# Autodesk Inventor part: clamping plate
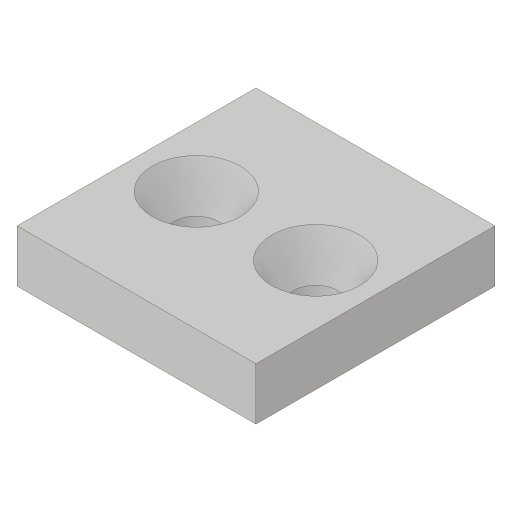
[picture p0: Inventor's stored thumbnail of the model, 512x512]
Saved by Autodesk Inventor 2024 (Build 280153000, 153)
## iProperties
Created: 2016-03
Part Number: clamping plate
Material: Generic
Document SubType Name: Modeling
Designer: Sandeep
Density: 1 g/cm^3
Appearance: Default
Mass: 6.41192 g
Surface Area: 30.6752 cm^2
Volume: 6.41192 cm^3
Author: Sandeep
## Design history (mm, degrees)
sketch "Sketch1"
  geometry: L1 (0, 0)-(32, 0); L2 (32, 0)-(32, 32); L3 (32, 32)-(0, 32); L4 (0, 32)-(0, 0)
  constraints: 8 end point, 2 parallel, 1 horizontal, 1 perpendicular
  dimensions: "d0" = 32 distance between parallel lines of L1 L3; "d1" = 32 distance of L2.end L3.end
extrude "Extrusion1" new body sketch "Sketch1" distance "d2" = 7; taper "d3" = 0 deg
hole "Hole2" diameter "d15" = 6; stored, may be unused: countersink angle "d19" = 60 deg, drill point angle "d21" = 118 deg; dims "d13" = 8, "d14" = 16, "d16" = 6, "d17" = 11.78, "d18" = 2, "d20" = 8
hole "Hole3" diameter "d24" = 6; stored, may be unused: countersink angle "d28" = 60 deg, drill point angle "d30" = 118 deg; dims "d22" = 8, "d23" = 16, "d25" = 6, "d26" = 11.78, "d27" = 2, "d29" = 8
body "Solid1"
sketch "Sketch2"
  geometry: 1 further point
sketch "Sketch3"
  geometry: 1 further point
sketch "Sketch4"
  geometry: 1 further point
